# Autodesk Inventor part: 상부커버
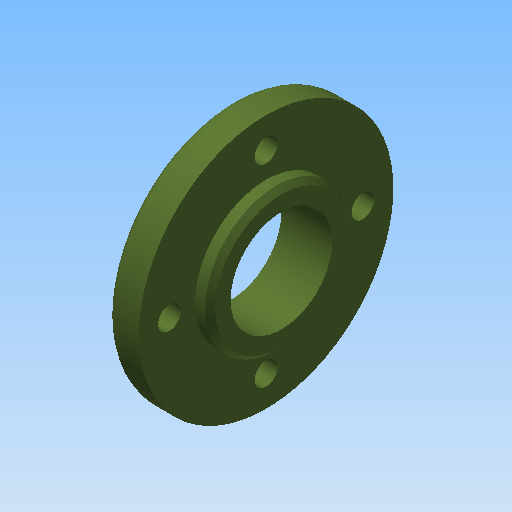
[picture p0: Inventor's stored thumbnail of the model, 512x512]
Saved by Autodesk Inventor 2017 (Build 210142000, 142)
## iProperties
Created: 2020-07
Part Number: 상부커버
Material: 알루미늄 6061
Document SubType Name: Modeling
Designer: mduedu
Density: 2.71 g/cm^3
Appearance: 올리브 녹색
Mass: 29.9794 g
Surface Area: 54.9099 cm^2
Volume: 11.0625 cm^3
Author: mduedu
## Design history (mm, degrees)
sketch "스케치1"
  geometry: L1 (0, 0)-(7, 0); L2 (7, 0)-(7, 25); L3 (7, 25)-(0, 25); L4 (0, 25)-(0, 0); L5 (7, 0)-(10, 0); L6 (10, 0)-(10, 14); L7 (10, 14)-(7, 14); L8 (7, 14)-(7, 0)
  constraints: 16 end point, 4 parallel, 2 horizontal, 2 perpendicular
  dimensions: "d0" = 50 diameter of L3 L1; "d2" = 28 diameter of L7 L5; "d3" = 7 distance of L2.end L3.end; "d4" = 10 distance between parallel lines of L6 L4
revolve "회전1" sketch "스케치1" stored, may be unused: angle "d5" = 90 deg
sketch "스케치2"
  geometry: C1 r 10 at (0, 0); 1 further point
  constraints: 1 centre point, 1 coincident
  dimensions: "d6" = 20 diameter of C1
extrude "돌출1" cut sketch "스케치2" stored distance "d7" = 10; taper "d8" = 0 deg
chamfer "모따기1" distance "d9" = 1; stored, may be unused: second distance "d10" = 2, angle "d11" = 45 deg
fillet "모깎기1" dims "d12" = 3
sketch "스케치3" dims "d13" = 38
  geometry: 3 further points
  constraints: 2 vertical alignment, 1 coincident, 2 other
hole "구멍1" sketch "스케치3" at (0, 19) diameter "d14" = 4.5; stored, may be unused: countersink angle "d18" = 90 deg, drill point angle "d20" = 118 deg; dims "d15" = 6, "d16" = 8, "d17" = 4.4, "d19" = 8
node "솔리드1"
pattern_circular "원형 패턴1" dims angle "d22" = 360 deg
